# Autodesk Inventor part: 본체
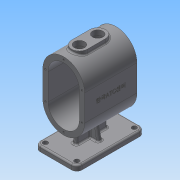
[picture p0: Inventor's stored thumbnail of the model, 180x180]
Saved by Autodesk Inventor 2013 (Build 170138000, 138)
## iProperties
Created: 2016-12
Part Number: 본체
Material: 알루미늄 6061
Document SubType Name: Modeling
Designer: mduedu
Density: 2.71 g/cm^3
Mass: 1171.02 g
Surface Area: 1014.94 cm^2
Volume: 432.112 cm^3
Author: mduedu
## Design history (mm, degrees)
sketch "스케치1"
  geometry: L1 (40, -25)-(40, 25); L2 (-40, 25)-(-40, -25); L3 (-40, -25)-(40, 25); L4 (40, -25)-(-40, 25); L5 (0, 25)-(0, -25); A1 r 40 centre (0, 25) between (40, 25) and (-40, 25); A2 r 40 centre (0, -25) between (-40, -25) and (40, -25); 1 further point
  constraints: 10 end point, 4 point on circle, 3 tangent, 2 centre point, 2 midpoint, 2 parallel, 1 vertical
  dimensions: "d0" = 130 dimension on A2 A1; "d2" = 80 distance between parallel lines of L1 L2
extrude "돌출1" new body sketch "스케치1" stored distance "d3" = 100; taper "d4" = 0 deg
feature "쉘1" dims "d5" = 10
sketch "스케치2"
  geometry: L1 (-90, 65)-(-100, 65); L2 (-100, 65)-(-100, -65); L3 (-100, -65)-(-90, -65); L4 (-90, -65)-(-90, 65); 2 further points
  constraints: 8 end point, 2 parallel, 1 horizontal, 1 horizontal alignment, 1 midpoint, 1 perpendicular
  dimensions: "d6" = 100 distance from line of L2 point (0, 0); "d7" = 130 distance of L1.end L2.end; "d8" = 10 distance of L2.end L3.end
extrude "돌출2" join sketch "스케치2" stored distance "d9" = 80; taper "d10" = 0 deg
fillet "모깎기1" dims "d11" = 10
sketch "스케치3"
  geometry: L1 (-10, 10)-(-10, 120) reference; L2 (60, 0)-(0, 0) reference; L3 (70, 120)-(70, 10) reference; L4 (0, 130)-(60, 130) reference; A1 r 10 centre (0, 120) between (0, 130) and (-10, 120) reference; A2 r 10 centre (0, 10) between (-10, 10) and (0, 0) reference; A3 r 10 centre (60, 10) between (60, 0) and (70, 10) reference; A4 r 10 centre (60, 120) between (70, 120) and (60, 130) reference; 5 further points
  constraints: 4 coincident
hole "구멍1" sketch "스케치3" at (60, 120), (60, 10), (0, 10), (0, 120) diameter "d12" = 9; stored, may be unused: countersink angle "d16" = 90 deg, drill point angle "d18" = 118 deg; dims "d13" = 6, "d14" = 4, "d15" = 2, "d17" = 8
sketch "스케치5"
  geometry: L1 (34, 35)-(26, 35); L2 (26, 35)-(26, 95); L3 (26, 95)-(34, 95); L4 (34, 95)-(34, 35); L5 (34, 35)-(26, 95); L6 (26, 35)-(34, 95); 1 further point
  constraints: 12 end point, 2 midpoint, 2 parallel, 1 horizontal, 1 perpendicular
  dimensions: "d22" = 8 distance of L2.end L3.end; "d24" = 60 distance of L1.end L2.end
extrude "돌출3" join sketch "스케치5" stored distance "d25" = 80; taper "d26" = 0 deg
feature "면 기울기1" dims angle "d27" = 5 deg
sketch "스케치6"
  geometry: L1 (-30, -90)-(30, -90) reference; L2 (-15.072, -62.052)-(-20, -90); A1 r 40 centre (0, -25) between (-40, -25) and (40, -25) reference; 1 further point
  constraints: 2 end point, 1 point on circle, 1 point on line
  dimensions: "d28" = 20 horizontal distance of A1.centre L2.end; "d29" = 80 deg angle of L2 L1
feature "리브1" sketch "스케치6" dims "d30" = 1, "d31" = 8, "d32" = 0, "d33" = 0, "d34" = 1, "d35" = 1
fillet "모깎기2" dims "d36" = 3
fillet "모깎기3" dims "d37" = 3, "d38" = 3
node "작업 평면1"
sketch "스케치9"
  geometry: 1 further point
sketch "스케치7"
  geometry: L1 (40, 50)-(-40, 50) reference; C1 r 15 at (0, 20); 1 further point
  constraints: 1 centre point, 1 vertical alignment
  dimensions: "d40" = 30 diameter of C1; "d41" = 30 distance from line of C1.centre L1
extrude "돌출4" join sketch "스케치7" stored distance "d42" = 80; taper "d43" = 0 deg
sketch "스케치15"
  geometry: C1 r 15 at (0, -15); C2 r 15 at (0, 20) reference; 1 further point
  constraints: 1 centre point, 1 vertical alignment
  dimensions: "d83" = 30 diameter of C1; "d84" = 35 distance of C1.centre C2.centre
extrude "돌출6" join sketch "스케치15" stored distance "d85" = 10; taper "d86" = 0 deg
hole "구멍2" diameter "d46" = 20; stored, may be unused: countersink angle "d50" = 90 deg, drill point angle "d52" = 118 deg; dims "d44" = 10, "d45" = 10, "d47" = 6, "d48" = 4, "d49" = 2, "d51" = 8
hole "구멍6" diameter "d89" = 20; stored, may be unused: countersink angle "d93" = 90 deg, drill point angle "d95" = 118 deg; dims "d87" = 10, "d88" = 10, "d90" = 6, "d91" = 4, "d92" = 2, "d94" = 8
node "작업 평면2"
sketch "스케치8"
  geometry: C1 r 15 at (0, 0) reference; C2 r 15 at (0, 0); 1 further point
  constraints: 1 centre point, 1 coincident
  dimensions: "d55" = 30 diameter of C2
extrude "돌출5" cut sketch "스케치8" stored distance "d56" = 80; taper "d57" = 0 deg
sketch "스케치16"
  geometry: C1 r 15 at (0, 35); 2 further points
  constraints: 1 centre point, 1 coincident, 1 vertical alignment
  dimensions: "d96" = 30 diameter of C1
extrude "돌출7" cut sketch "스케치16" stored distance "d97" = 10; taper "d98" = 0 deg
sketch "스케치17"
  geometry: L1 (15, 0)-(15, -35); L2 (-15, 0)-(-15, -35); C1 r 10 at (0, 0) reference; C2 r 10 at (0, -35) reference; A1 r 15 centre (0, 0) between (15, 0) and (-15, 0) reference; A2 r 15 centre (0, -35) between (15, -35) and (-15, -35) reference; 1 further point
  constraints: 4 end point, 4 point on circle, 3 tangent, 1 vertical
extrude "돌출8" join sketch "스케치17" stored distance "d99" = 10; taper "d100" = 0 deg
fillet "모깎기5" dims "d101" = 3
chamfer "모따기1" distance "d58" = 1; stored, may be unused: second distance "d59" = 2, angle "d60" = 45 deg
sketch "스케치10"
  geometry: 2 further points
  constraints: 1 coincident, 1 other
feature "엠보싱1" sketch "스케치10" dims "d0" = 130, "d2" = 80, "d11" = 10, "d61" = 0.5, "d62" = 0
sketch "스케치11"
  geometry: 1 further point
hole "구멍3" sketch "스케치11" at (0, 60) diameter "d63" = 3.242; stored, may be unused: countersink angle "d67" = 90 deg, drill point angle "d69" = 120 deg; dims "d64" = 8.6, "d65" = 4, "d66" = 2, "d68" = 10.6
sketch "스케치12"
  geometry: 1 further point
hole "구멍5" sketch "스케치12" at (0, 60) diameter "d70" = 3.242; stored, may be unused: countersink angle "d74" = 90 deg, drill point angle "d76" = 120 deg; dims "d71" = 8.6, "d72" = 4, "d73" = 2, "d75" = 10.6
node "솔리드1"
mirror "대칭1"
pattern_linear "직사각형 패턴1"
pattern_linear "직사각형 패턴2"
node "투영된 루프1"
sketch "스케치13"
  geometry: L1 (-40, 25)-(-40, -25) reference; L2 (40, -25)-(40, 25) reference; L3 (35, 25)-(35, -25); L4 (-35, -25)-(-35, 25); A1 r 40 centre (0, 25) between (40, 25) and (-40, 25) reference; A2 r 40 centre (0, -25) between (-40, -25) and (40, -25) reference; A3 r 35 centre (0, 25) between (35, 25) and (-35, 25); A4 r 35 centre (0, -25) between (-35, -25) and (35, -25); 2 further points
  constraints: 5 point on circle, 4 end point, 2 centre point, 3 other
  dimensions: "d77" = 5 distance between parallel lines of L3 L2
sketch "스케치14"
  geometry: L1 (-40, 25)-(-40, -25) reference; L2 (40, -25)-(40, 25) reference; L3 (35, 25)-(35, -25); L4 (-35, -25)-(-35, 25); A1 r 40 centre (0, 25) between (40, 25) and (-40, 25) reference; A2 r 40 centre (0, -25) between (-40, -25) and (40, -25) reference; A3 r 35 centre (0, 25) between (35, 25) and (-35, 25); A4 r 35 centre (0, -25) between (-35, -25) and (35, -25); 2 further points
  constraints: 5 point on circle, 4 end point, 2 centre point, 3 other
  dimensions: "d80" = 5 distance between parallel lines of L2 L3
node "투영된 루프3"
node "투영된 루프4"
node "투영된 루프5"
